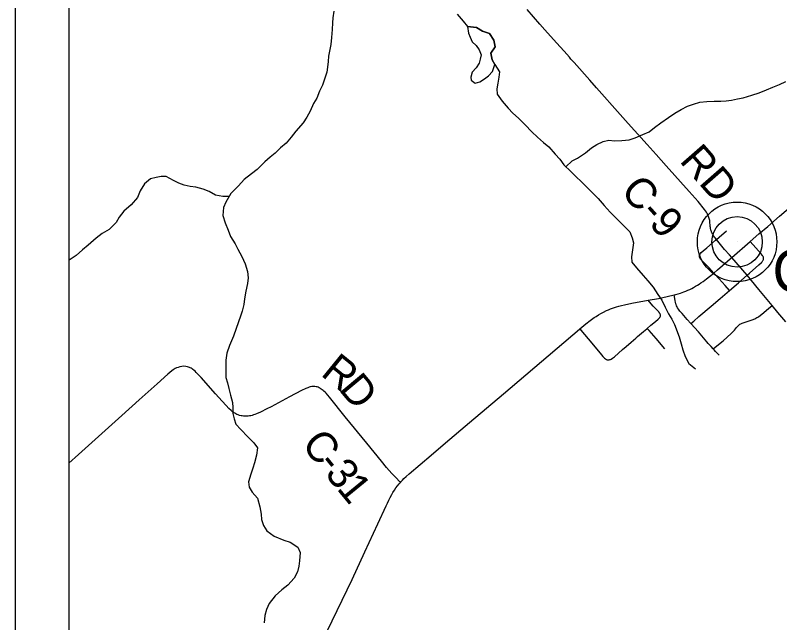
# Model space of a CAD drawing. Extents: x 0 to 34, y 0 to 22.
# Drawn here: x 2 to 3.432, y 18.098 to 19.235 of the extents above; entities that cross this region are included whole.
import ezdxf

# ---------------------------------------------------------------- set-up
doc = ezdxf.new("R2010")
doc.units = 0
for name, color, linetype in [('Default', 7, 'Continuous'), ('GM_X_County_Road', 7, 'Continuous'), ('GM_X_County_Road_Text', 7, 'Continuous'), ('GM_X_Minor_Lake', 7, 'Continuous'), ('GM_X_Minor_River', 7, 'Continuous'), ('GM_X_State_Route', 7, 'Continuous'), ('GM_X_Township_Road', 7, 'Continuous'), ('GM_X_Unincorporated', 7, 'Continuous'), ('GM_X_Unincorporated_Location', 7, 'Continuous'), ('GM_X_Unincorporated_Text', 7, 'Continuous'), ('SH_Cut_Line', 7, 'Continuous'), ('SH_Data', 7, 'Continuous')]:
    doc.layers.add(name, color=color, linetype=linetype)

msp = doc.modelspace()

# ---------------------------------------------------------------- linework, layer by layer
at = {"layer": 'Default'}
msp.add_lwpolyline([(6.6858, 19.0362), (6.6949, 19.1537), (6.8302, 20.9), (3.1229, 20.9), (2.9275, 20.8467), (2.2946, 20.6707), (2.1, 20.6202), (2.1, 17.1279), (2.1211, 17.1003), (3.2076, 15.5689), (3.4902, 15.1704), (4.0558, 14.3671), (4.1658, 14.2105), (4.302, 14.3105), (5.6165, 15.2674), (6.0871, 15.6176), (6.2834, 15.7529), (6.4392, 15.8657), (6.5428, 17.1931), (6.5451, 17.2211), (6.6309, 18.3364), (6.6363, 18.3979), (6.6654, 18.7733)], dxfattribs=at)
at = {"layer": 'GM_X_County_Road'}
msp.add_line((3.3705, 18.7481), (3.3421, 18.7815), dxfattribs=at)
for points in [[(3.3131, 18.8149), (3.3105, 18.8179), (3.3094, 18.8195), (3.3083, 18.821), (3.3076, 18.822), (3.3069, 18.8232), (3.3063, 18.8242), (3.3057, 18.8253), (3.3052, 18.8266), (3.3047, 18.8276), (3.3042, 18.8288), (3.3037, 18.8301), (3.3033, 18.8315), (3.3027, 18.833), (3.3022, 18.8354), (3.3018, 18.8374), (3.3016, 18.8391), (3.3014, 18.8411), (3.3012, 18.843), (3.3009, 18.8458), (3.3007, 18.8484), (3.3005, 18.8504), (3.3, 18.8526), (3.2996, 18.8545), (3.2991, 18.856), (3.2985, 18.858), (3.2977, 18.8599), (3.2968, 18.8619), (3.2957, 18.8638), (3.2944, 18.8661), (3.2926, 18.8686), (3.2908, 18.8711), (3.2787, 18.886), (3.262, 18.9051), (3.2193, 18.9528), (3.2002, 18.9741), (3.1837, 18.9926), (3.1481, 19.0324), (3.1331, 19.049), (3.0885, 19.0992), (3.0763, 19.1132), (3.0466, 19.1461), (3.043, 19.1501), (3.0406, 19.1529), (3.0377, 19.1562), (3.028, 19.1675), (3.0138, 19.1832), (2.9919, 19.2078), (2.9823, 19.2184), (2.9586, 19.2455)], [(3.3421, 18.7815), (3.3378, 18.7863), (3.3285, 18.7964), (3.3131, 18.8149)], [(3.4175, 18.6915), (3.3928, 18.7216), (3.3705, 18.7481)], [(3.4432, 18.6609), (3.4283, 18.6784), (3.4175, 18.6915)], [(2.7213, 18.3604), (2.7115, 18.3705), (2.705, 18.3772), (2.6955, 18.388), (2.6856, 18.3999), (2.6582, 18.4338), (2.6176, 18.4832), (2.5884, 18.5196), (2.582, 18.5271), (2.5801, 18.5291), (2.5781, 18.5311), (2.5766, 18.5325), (2.5749, 18.5338), (2.5731, 18.5351), (2.5714, 18.5363), (2.5693, 18.5374), (2.5673, 18.5384), (2.5654, 18.539), (2.5637, 18.5394), (2.5611, 18.5399), (2.559, 18.54), (2.5555, 18.5396), (2.5525, 18.5391), (2.5502, 18.5385), (2.5479, 18.5376), (2.544, 18.5359), (2.5362, 18.5321), (2.5136, 18.5203), (2.479, 18.502), (2.4713, 18.4979), (2.459, 18.4917), (2.4516, 18.4884), (2.4487, 18.4874), (2.4462, 18.4866), (2.4434, 18.4858), (2.4412, 18.4851), (2.4389, 18.4847), (2.4363, 18.4844), (2.4342, 18.4842), (2.4319, 18.4841), (2.4296, 18.4842), (2.4275, 18.4842), (2.4252, 18.4846), (2.4231, 18.4849), (2.42, 18.4856), (2.4174, 18.4865), (2.4152, 18.4873), (2.4129, 18.4885), (2.4109, 18.4898), (2.4086, 18.4912), (2.4063, 18.4931), (2.4042, 18.4948), (2.4001, 18.4987), (2.395, 18.5042), (2.3876, 18.5126), (2.3751, 18.5264), (2.3483, 18.5566), (2.3415, 18.5638), (2.339, 18.5662), (2.3366, 18.5685), (2.3345, 18.5701), (2.3328, 18.5716), (2.3311, 18.5726), (2.3292, 18.5739), (2.3275, 18.5747), (2.326, 18.5755), (2.3226, 18.5767), (2.3191, 18.5774), (2.3155, 18.5776), (2.3119, 18.5773), (2.3083, 18.5767), (2.3048, 18.5757), (2.302, 18.5746), (2.2996, 18.5735), (2.2977, 18.5723), (2.2957, 18.5709), (2.2932, 18.5692), (2.2858, 18.5627), (2.2658, 18.5449), (2.2321, 18.5146), (2.1997, 18.4855), (2.1181, 18.4127), (2.1, 18.3964)]]:
    msp.add_lwpolyline(points, dxfattribs=at)
at = {"layer": 'GM_X_Minor_Lake'}
for points in [[(2.8469, 19.2138), (2.849, 19.2014), (2.852, 19.1937), (2.8557, 19.185), (2.8632, 19.178), (2.8688, 19.17), (2.8725, 19.1608), (2.8709, 19.1529), (2.8689, 19.1453), (2.8631, 19.1366), (2.8558, 19.128), (2.8534, 19.1189), (2.8541, 19.1132), (2.8612, 19.1074), (2.87, 19.1103), (2.8785, 19.1156), (2.8861, 19.1216), (2.8938, 19.1294), (2.8982, 19.1425)], [(2.8982, 19.1425), (2.8933, 19.1511), (2.8904, 19.1637), (2.8986, 19.1757), (2.8964, 19.1879), (2.8882, 19.2006), (2.8753, 19.2053), (2.8636, 19.2119), (2.8469, 19.2138)]]:
    msp.add_lwpolyline(points, dxfattribs=at)
at = {"layer": 'GM_X_Minor_River'}
for points in [[(2.5965, 19.2426), (2.5949, 19.2301), (2.594, 19.2206), (2.5935, 19.2081), (2.5921, 19.1933), (2.5908, 19.1804), (2.5892, 19.1705), (2.5868, 19.158), (2.5859, 19.1481), (2.585, 19.1379), (2.5837, 19.1284), (2.579, 19.1151), (2.5751, 19.1042), (2.5696, 19.0928), (2.5645, 19.0796), (2.5583, 19.0694), (2.5524, 19.055), (2.5462, 19.0441), (2.5392, 19.0335), (2.5253, 19.0177), (2.5168, 19.0064), (2.5076, 18.9955), (2.4964, 18.9869), (2.4868, 18.9767), (2.4772, 18.9689), (2.4672, 18.9602), (2.4533, 18.9463), (2.4422, 18.9377), (2.4284, 18.9272), (2.418, 18.9156), (2.4037, 18.9009), (2.3944, 18.8851), (2.3897, 18.8749), (2.3884, 18.8601), (2.3932, 18.846), (2.3987, 18.8326), (2.4031, 18.8208), (2.4117, 18.807), (2.4165, 18.7971), (2.4244, 18.7829), (2.4303, 18.7696), (2.4347, 18.7551), (2.4361, 18.7433), (2.4352, 18.7326), (2.432, 18.7186), (2.4295, 18.7042), (2.4282, 18.6932), (2.425, 18.6811), (2.4215, 18.6713), (2.4136, 18.6485), (2.4085, 18.6342), (2.4014, 18.6168), (2.3959, 18.6024), (2.3942, 18.5891), (2.3941, 18.5789), (2.3944, 18.5667), (2.3946, 18.5568), (2.3972, 18.5469), (2.4001, 18.5359), (2.403, 18.5233), (2.4066, 18.51), (2.4076, 18.5004), (2.4075, 18.4891), (2.4097, 18.4795), (2.4133, 18.4696), (2.4224, 18.4596), (2.4355, 18.4458), (2.4468, 18.4343), (2.4535, 18.4247), (2.4515, 18.4114), (2.4479, 18.397), (2.4451, 18.3868), (2.4411, 18.3758), (2.4368, 18.3611), (2.4378, 18.3516), (2.4438, 18.342), (2.4535, 18.3309), (2.4583, 18.3145), (2.4608, 18.3008), (2.4614, 18.2909), (2.4647, 18.2795), (2.471, 18.2695)], [(2.8274, 19.2366), (2.839, 19.2235), (2.8469, 19.2138), (2.8636, 19.2119), (2.8753, 19.2053), (2.8882, 19.2006), (2.8964, 19.1879), (2.8986, 19.1757), (2.8904, 19.1637), (2.8933, 19.1511), (2.8982, 19.1425), (2.9068, 19.1289), (2.9059, 19.1187), (2.9035, 19.1077), (2.9018, 19.0971), (2.9025, 19.0872), (2.9118, 19.0741), (2.9231, 19.0611), (2.9317, 19.0515), (2.9422, 19.0419), (2.955, 19.03), (2.9674, 19.0165), (2.9783, 19.0069), (2.9893, 18.9969), (2.9994, 18.9884), (3.0114, 18.975), (3.0201, 18.9654), (3.0276, 18.9551), (3.0403, 18.9424), (3.0497, 18.9328), (3.0603, 18.9228), (3.0716, 18.9116), (3.0813, 18.9024), (3.0915, 18.892), (3.1027, 18.8786), (3.1144, 18.8663), (3.1268, 18.8536), (3.1384, 18.8421), (3.1512, 18.8291), (3.1553, 18.8184), (3.1578, 18.8088), (3.1561, 18.7956), (3.1541, 18.7823), (3.1547, 18.7724), (3.1633, 18.762), (3.1757, 18.7475), (3.1847, 18.7375), (3.1949, 18.726), (3.2035, 18.7122), (3.2106, 18.7015), (3.2172, 18.6885), (3.2236, 18.6759), (3.2295, 18.6656), (3.2344, 18.656), (3.2432, 18.6331), (3.2469, 18.6198), (3.2501, 18.6087), (3.2549, 18.5957), (3.2616, 18.5828), (3.2737, 18.5727)], [(3.0314, 18.9512), (3.0432, 18.9621), (3.0532, 18.9673), (3.0678, 18.9774), (3.0793, 18.9868), (3.0889, 18.9927), (3.1011, 18.9987), (3.1114, 19.0012), (3.1225, 19), (3.1358, 19.0002), (3.1495, 19.0016), (3.161, 19.0056), (3.1755, 19.0115), (3.187, 19.0167), (3.1973, 19.0246), (3.2092, 19.0336), (3.2234, 19.0437), (3.2353, 19.0515), (3.2472, 19.0582), (3.2591, 19.0645), (3.2701, 19.0686), (3.282, 19.0723), (3.2953, 19.0736), (3.309, 19.0742), (3.3216, 19.0737), (3.3311, 19.0747), (3.3414, 19.0761), (3.3528, 19.0783), (3.3635, 19.0805), (3.3792, 19.0852), (3.3929, 19.0896), (3.4071, 19.0955), (3.4189, 19.1003), (3.4311, 19.1055), (3.4434, 19.1111)], [(2.4006, 18.8957), (2.3888, 18.8958), (2.3751, 18.8982), (2.363, 18.9048), (2.3521, 18.9091), (2.338, 18.9127), (2.3278, 18.9143), (2.3164, 18.9167), (2.3062, 18.9203), (2.296, 18.9257), (2.2827, 18.9327), (2.2732, 18.9328), (2.2637, 18.931), (2.253, 18.9288), (2.2419, 18.9195), (2.2337, 18.9063), (2.2286, 18.8938), (2.217, 18.8802), (2.2032, 18.8682), (2.1943, 18.8569), (2.1892, 18.8471), (2.1758, 18.8336), (2.1627, 18.8261), (2.1512, 18.8175), (2.1362, 18.8044), (2.1258, 18.7958), (2.1139, 18.7849), (2.1009, 18.7763), (2.1, 18.7759)], [(2.471, 18.2695), (2.4846, 18.2599), (2.5028, 18.2521), (2.5149, 18.2481), (2.5289, 18.2388), (2.5337, 18.2293), (2.532, 18.2137), (2.5311, 18.2035), (2.5283, 18.1929), (2.5225, 18.1808), (2.5105, 18.168), (2.4994, 18.1594), (2.4867, 18.1481), (2.4755, 18.1338), (2.4704, 18.1225), (2.4676, 18.1111), (2.4659, 18.0975)]]:
    msp.add_lwpolyline(points, dxfattribs=at)
at = {"layer": 'GM_X_State_Route'}
for points in [[(3.3764, 18.8114), (3.3928, 18.8255), (3.4093, 18.8396), (3.4315, 18.8585), (3.4767, 18.8975)], [(3.0571, 18.6477), (3.0684, 18.6571), (3.0768, 18.6635), (3.0844, 18.6688), (3.0881, 18.6711), (3.0923, 18.6737), (3.0966, 18.6763), (3.1014, 18.6789), (3.1075, 18.6819), (3.1109, 18.6834), (3.1149, 18.685), (3.1187, 18.6864), (3.1225, 18.6877), (3.1261, 18.6888), (3.1302, 18.69), (3.1353, 18.6913), (3.141, 18.6927), (3.1549, 18.6957), (3.1855, 18.7013), (3.2044, 18.7048), (3.2209, 18.7083), (3.2339, 18.7114), (3.2372, 18.7122), (3.2456, 18.7146), (3.2521, 18.7168), (3.2561, 18.7184), (3.2596, 18.7199), (3.2632, 18.7216), (3.267, 18.7235), (3.2699, 18.7251), (3.2741, 18.7274), (3.2777, 18.7296), (3.281, 18.7316), (3.2842, 18.7339), (3.2881, 18.7367), (3.2944, 18.7415), (3.3, 18.7458), (3.308, 18.7523), (3.3154, 18.7584), (3.3245, 18.7662), (3.3389, 18.7787), (3.3421, 18.7815), (3.3764, 18.8114)], [(2.5755, 18.0634), (2.6031, 18.1204), (2.6309, 18.1788), (2.6547, 18.2301), (2.6789, 18.2826), (2.6945, 18.3164), (2.6969, 18.3215), (2.6997, 18.3271), (2.7021, 18.332), (2.7051, 18.3375), (2.7072, 18.3412), (2.7101, 18.3457), (2.7129, 18.35), (2.7158, 18.3537), (2.7189, 18.3578), (2.7213, 18.3604), (2.7226, 18.362), (2.7252, 18.3646), (2.7278, 18.3673), (2.7322, 18.3714), (2.7378, 18.3765), (2.7786, 18.411), (2.806, 18.4344), (2.8505, 18.4722), (2.9146, 18.5264), (3.0565, 18.6472), (3.0571, 18.6477)]]:
    msp.add_lwpolyline(points, dxfattribs=at)
at = {"layer": 'GM_X_Township_Road'}
for points in [[(3.3131, 18.8149), (3.318, 18.8193), (3.3323, 18.8311)], [(3.2818, 18.7865), (3.2824, 18.7876), (3.2836, 18.789), (3.2848, 18.7905), (3.2885, 18.7937), (3.2952, 18.7993), (3.3059, 18.8086), (3.3115, 18.8135), (3.3131, 18.8149)], [(3.3705, 18.7481), (3.375, 18.7521), (3.3928, 18.7678), (3.3974, 18.772), (3.3985, 18.7732), (3.3995, 18.7744), (3.4003, 18.7755), (3.4008, 18.7765), (3.4011, 18.7777), (3.4014, 18.7795), (3.4011, 18.7813), (3.4006, 18.783), (3.4, 18.7841), (3.3993, 18.7852), (3.3966, 18.7886), (3.387, 18.7993), (3.3764, 18.8114)], [(3.308, 18.7523), (3.2994, 18.7619), (3.2951, 18.7664), (3.2889, 18.7726), (3.285, 18.7766), (3.2834, 18.7785), (3.2821, 18.7805), (3.2814, 18.7822), (3.2812, 18.7841), (3.2813, 18.7853), (3.2818, 18.7865)], [(3.3374, 18.7196), (3.3294, 18.7287), (3.3182, 18.7412), (3.3093, 18.7508), (3.308, 18.7523)], [(3.3374, 18.7196), (3.3542, 18.7342), (3.3705, 18.7481)], [(3.2654, 18.6576), (3.2709, 18.6624), (3.2801, 18.6707), (3.3034, 18.6903), (3.3199, 18.7045), (3.3374, 18.7196)], [(3.1836, 18.6485), (3.1901, 18.6545), (3.1988, 18.6615), (3.204, 18.6659), (3.2063, 18.6681), (3.2069, 18.6688), (3.2074, 18.6696), (3.2078, 18.6703), (3.2081, 18.6713), (3.2082, 18.6725), (3.2081, 18.6743), (3.2078, 18.6752), (3.2075, 18.6761), (3.2068, 18.6772), (3.2063, 18.6783), (3.2055, 18.6793), (3.2047, 18.6802), (3.2008, 18.6842), (3.1947, 18.6904), (3.1911, 18.6947), (3.1855, 18.7013)], [(3.2487, 18.6765), (3.2449, 18.6809), (3.2436, 18.6827), (3.2419, 18.6849), (3.2405, 18.687), (3.2393, 18.6892), (3.2385, 18.691), (3.2378, 18.6931), (3.2373, 18.6946), (3.2367, 18.6974), (3.2361, 18.7001), (3.2352, 18.7044), (3.2339, 18.7114)], [(3.307, 18.6104), (3.3138, 18.6159), (3.3259, 18.6256), (3.3335, 18.6321), (3.3407, 18.6388), (3.3426, 18.6407), (3.3446, 18.6428), (3.3468, 18.6453), (3.3487, 18.6475), (3.351, 18.6502), (3.353, 18.6528), (3.3558, 18.6553), (3.3572, 18.6565), (3.3589, 18.6573), (3.3615, 18.6583), (3.3635, 18.6591), (3.3669, 18.6602), (3.3765, 18.6631), (3.3818, 18.665), (3.3834, 18.6658), (3.3851, 18.6666), (3.3869, 18.6675), (3.3889, 18.6687), (3.3906, 18.6698), (3.3925, 18.6711), (3.3979, 18.6753), (3.4104, 18.6856), (3.4175, 18.6915)], [(3.2654, 18.6576), (3.2584, 18.6654), (3.2518, 18.6728), (3.2487, 18.6765)], [(3.307, 18.6104), (3.3031, 18.6146), (3.3, 18.6178), (3.2974, 18.6205), (3.2949, 18.6233), (3.2794, 18.6419), (3.2654, 18.6576)], [(3.0571, 18.6477), (3.0624, 18.6415), (3.0766, 18.6244), (3.0981, 18.599), (3.1005, 18.5962), (3.1035, 18.5928), (3.1056, 18.5914), (3.107, 18.5906), (3.1086, 18.59), (3.1099, 18.5898)], [(3.1099, 18.5898), (3.1112, 18.5897), (3.1124, 18.5898), (3.1138, 18.5901), (3.1147, 18.5904), (3.1159, 18.591), (3.1186, 18.5926), (3.122, 18.5953), (3.1373, 18.609), (3.1439, 18.6146), (3.1537, 18.6231), (3.1622, 18.6304), (3.1655, 18.6332), (3.1768, 18.6428), (3.183, 18.648), (3.1836, 18.6485)], [(3.2166, 18.6101), (3.2001, 18.6295), (3.1872, 18.6444), (3.1836, 18.6485)], [(3.3181, 18.5987), (3.3117, 18.6055), (3.309, 18.6083), (3.307, 18.6104)]]:
    msp.add_lwpolyline(points, dxfattribs=at)
at = {"layer": 'GM_X_Unincorporated'}
for radius in [0.0744, 0.0472]:
    msp.add_circle((3.3519, 18.8106), radius, dxfattribs=at)
at = {"layer": 'GM_X_Unincorporated_Location'}
msp.add_line((3.3519, 18.8106), (3.3519, 18.8106), dxfattribs=at)
at = {"layer": 'SH_Cut_Line'}
msp.add_lwpolyline([(6.6858, 19.0362), (6.6949, 19.1537), (6.8302, 20.9), (2.1, 20.9), (2.1, 14.1), (4.022, 14.1), (4.1658, 14.2105), (4.302, 14.3105), (5.6165, 15.2674), (6.0871, 15.6176), (6.2834, 15.7529), (6.4392, 15.8657), (6.5428, 17.1931), (6.5451, 17.2211), (6.6309, 18.3364), (6.6363, 18.3979), (6.6654, 18.7733)], dxfattribs=at)
at = {"layer": 'SH_Data'}
for p, q in [((2, 21), (2, 14)), ((2.1, 20.9), (2.1, 14.1))]:
    msp.add_line(p, q, dxfattribs=at)

# ---------------------------------------------------------------- texts
at = {"layer": 'GM_X_County_Road_Text'}
for s, height, rotation, p in [('RD', 0.05682, 311.1845, (3.2424, 18.9617)), ('C-9', 0.05682, 311.8365, (3.1316, 18.904)), ('R', 0.0568, 320.8721, (2.5702, 18.5618)), ('D', 0.0568, 309.9063, (2.6044, 18.5344)), ('C', 0.0568, 308.7171, (2.5344, 18.431)), ('-', 0.0568, 308.7484, (2.5636, 18.3946)), ('3', 0.0568, 308.8447, (2.5783, 18.3763)), ('1', 0.0568, 309.342, (2.6006, 18.3486))]:
    msp.add_text(s, height=height, rotation=rotation, dxfattribs=at).set_placement(p)
at = {"layer": 'GM_X_Unincorporated_Text'}
msp.add_text('Centerville', height=0.078977, rotation=0, dxfattribs=at).set_placement((3.4181, 18.7169))

doc.saveas('drawing.dxf')
